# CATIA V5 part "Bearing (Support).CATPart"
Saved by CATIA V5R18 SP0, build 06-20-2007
Part number: Bearing (Support)
Bounding box of the stored display mesh (mm): x -270 to 10, y -39.842 to 39.842, z -34.808 to 139.842
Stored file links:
  D:\shriniwas\v5_r19\c16_CAT_v5r19\c16_Part\CV Joint\Support.CATPart
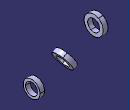
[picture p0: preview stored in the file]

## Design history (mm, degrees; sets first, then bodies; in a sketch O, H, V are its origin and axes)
Body1 (main body)
  Sketch1 on yz-plane, origin (0, 0, 0), H (0, 1, 0), V (0, 0, 1)
    circle A1 centre (0, 0) radius 25
    circle A2 centre (0, 0) radius 35
    radius A1 = 25
    radius A2 = 35
  Pad1: profile Sketch1, direction (1, 0, 0), length 10, mirrored extent
  Sketch2 on zx-plane, origin (0, 0, 0), H (-1, 0, 0), V (0, 0, 1)
    construction line L1 (0, 0) -> (60, 0)
    construction line L2 (60, 0) -> (194.1972, 77.4788)
    line L3 (107.5, 56.2917) -> (124.8205, 66.2917)
    line L4 (124.8205, 66.2917) -> (117.3205, 79.282)
    line L5 (117.3205, 79.282) -> (100, 69.282)
    point P6 (100, 69.282)
    line L6 (100, 69.282) -> (107.5, 56.2917)
    angle L2 L1 = 30
    distance L6 L4 = 20
    length L6 = 15
    distance L3 L2 = 25
    distance P6 V = 100
    length L1 = 60
    horizontal: L1 H
    perpendicularity: L4 L3
    parallelism: L5 L2, L6 L4
  Sketch3 on zx-plane, origin (0, 0, 0), H (-1, 0, 0), V (0, 0, 1)
    line L1 (60, 0) -> (221.9169, 93.4828)
    point P1 (60, 0)
    reference projected line E1 (107.5, 56.2917) -> (124.8205, 66.2917) from Sketch2.L3
    reference projected line E2 (107.5, 56.2917) -> (124.8205, 66.2917) from Sketch2.L3
    distance E2 L1 = 25
    coincidence: P1 H
    parallelism: L1 E1
  Shaft1: profile Sketch2, axis Sketch3.L1, angle 360
  Sketch4 on zx-plane, origin (0, 0, 0), H (-1, 0, 0), V (0, 0, 1)
    construction line L1 (188.3301, 100) -> (395.6544, 100)
    point P3 (260, 132.5)
    line L2 (270, 140) -> (270, 125)
    line L3 (270, 125) -> (250, 125)
    line L4 (250, 125) -> (250, 140)
    line L5 (250, 140) -> (270, 140)
    distance L1 H = 100
    length L5 = 20
    length L4 = 15
    distance L1 L3 = 25
    distance L4 V = 250
    horizontal: L1 H, L3 H, L5 H
    vertical: L2 V, L4 V
    equidistance: L2 L4 P3, L3 L5 P3
  Sketch5 on zx-plane, origin (0, 0, 0), H (-1, 0, 0), V (0, 0, 1)
    line L1 (210.3804, 100) -> (348.9415, 100)
    reference projected line E1 (250, 125) -> (270, 125) from Sketch4.L3
    distance L1 E1 = 25
    horizontal: L1 H
  Shaft2: profile Sketch4, axis Sketch5.L1, angle 360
